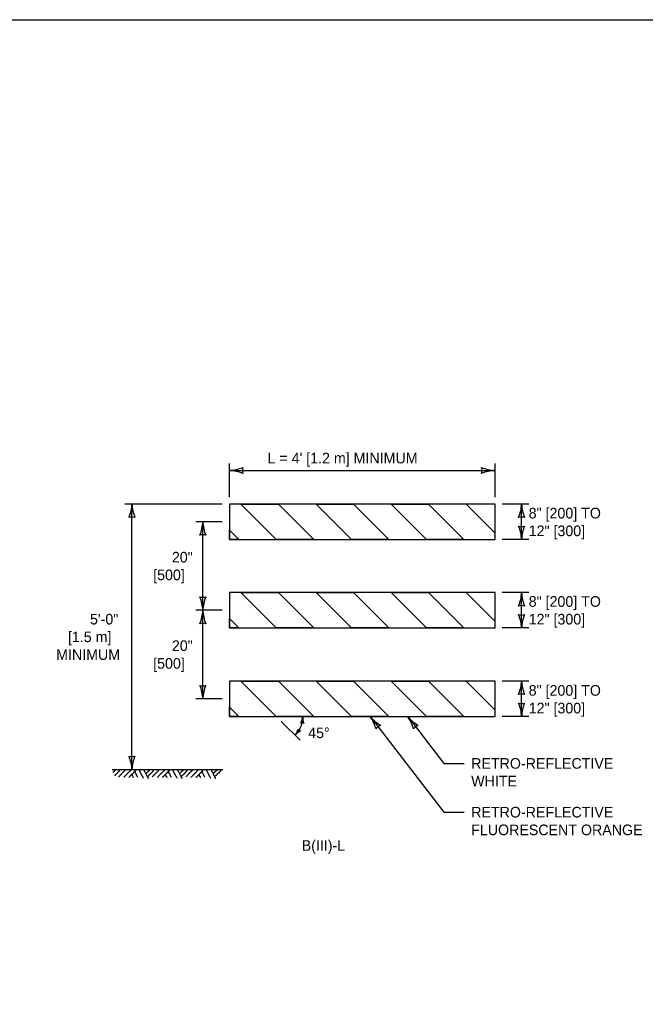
# Model space of a CAD drawing. Extents: x 49991.4 to 50021, y 49987.6 to 50011.4.
# Drawn here: x 50005.22 to 50008.75, y 49993.4 to 49999 of the extents above; entities that cross this region are included whole.
import ezdxf

# ---------------------------------------------------------------- set-up
doc = ezdxf.new("R2010")
doc.units = 0
for name, color, linetype in [('Level 1', 7, 'Continuous'), ('Level 2', 7, 'Continuous'), ('Level 3', 7, 'Continuous')]:
    doc.layers.add(name, color=color, linetype=linetype)

msp = doc.modelspace()

# ---------------------------------------------------------------- linework, layer by layer
at = {"layer": 'Level 1'}
for p, q in [((50006.6636, 49996.0636), (50006.464, 49996.2636)), ((50006.6636, 49996.0636), (50006.464, 49996.2636)), ((50006.8756, 49996.0636), (50006.676, 49996.2636)), ((50006.676, 49996.2636), (50006.8756, 49996.0636)), ((50007.0875, 49996.0636), (50006.8879, 49996.2636)), ((50007.0875, 49996.0636), (50006.8879, 49996.2636)), ((50007.2995, 49996.0636), (50007.0999, 49996.2636)), ((50007.0999, 49996.2636), (50007.2995, 49996.0636)), ((50007.5114, 49996.0636), (50007.3118, 49996.2636)), ((50007.5114, 49996.0636), (50007.3118, 49996.2636)), ((50007.7234, 49996.0636), (50007.5238, 49996.2636)), ((50007.5238, 49996.2636), (50007.7234, 49996.0636)), ((50007.8988, 49996.1002), (50007.7357, 49996.2636)), ((50007.7357, 49996.2636), (50007.8988, 49996.1002)), ((50006.4517, 49996.0636), (50006.3988, 49996.1166)), ((50006.3988, 49996.1166), (50006.4517, 49996.0636)), ((50006.6636, 49995.5636), (50006.464, 49995.7636)), ((50006.6636, 49995.5636), (50006.464, 49995.7636)), ((50006.8756, 49995.5636), (50006.676, 49995.7636)), ((50006.676, 49995.7636), (50006.8756, 49995.5636)), ((50007.0875, 49995.5636), (50006.8879, 49995.7636)), ((50007.0875, 49995.5636), (50006.8879, 49995.7636)), ((50007.2995, 49995.5636), (50007.0999, 49995.7636)), ((50007.0999, 49995.7636), (50007.2995, 49995.5636)), ((50007.5114, 49995.5636), (50007.3118, 49995.7636)), ((50007.5114, 49995.5636), (50007.3118, 49995.7636)), ((50007.7234, 49995.5636), (50007.5238, 49995.7636)), ((50007.5238, 49995.7636), (50007.7234, 49995.5636)), ((50007.8988, 49995.6002), (50007.7357, 49995.7636)), ((50007.7357, 49995.7636), (50007.8988, 49995.6002)), ((50006.4517, 49995.5636), (50006.3988, 49995.6166)), ((50006.3988, 49995.6166), (50006.4517, 49995.5636)), ((50006.6636, 49995.0636), (50006.464, 49995.2636)), ((50006.6636, 49995.0636), (50006.464, 49995.2636)), ((50006.8756, 49995.0636), (50006.676, 49995.2636)), ((50006.676, 49995.2636), (50006.8756, 49995.0636)), ((50007.0875, 49995.0636), (50006.8879, 49995.2636)), ((50007.0875, 49995.0636), (50006.8879, 49995.2636)), ((50007.2995, 49995.0636), (50007.0999, 49995.2636)), ((50007.0999, 49995.2636), (50007.2995, 49995.0636)), ((50007.5114, 49995.0636), (50007.3118, 49995.2636)), ((50007.5114, 49995.0636), (50007.3118, 49995.2636)), ((50007.7234, 49995.0636), (50007.5238, 49995.2636)), ((50007.5238, 49995.2636), (50007.7234, 49995.0636)), ((50007.8988, 49995.1002), (50007.7357, 49995.2636)), ((50007.7357, 49995.2636), (50007.8988, 49995.1002)), ((50006.4517, 49995.0636), (50006.3988, 49995.1166)), ((50006.3988, 49995.1166), (50006.4517, 49995.0636))]:
    msp.add_line(p, q, dxfattribs=at)
for points in [[(49999.3835, 49998.9992), (50016.7501, 49998.9992), (50016.7501, 49987.7988), (49999.3835, 49987.7988)], [(50007.8988, 49996.2636), (50006.3988, 49996.2636), (50006.3988, 49996.0636), (50007.8988, 49996.0636)], [(50007.8988, 49995.7636), (50006.3988, 49995.7636), (50006.3988, 49995.5636), (50007.8988, 49995.5636)], [(50007.8988, 49995.2636), (50006.3988, 49995.2636), (50006.3988, 49995.0636), (50007.8988, 49995.0636)]]:
    msp.add_lwpolyline(points, close=True, dxfattribs=at)
for points in [[(50006.464, 49996.2636), (50006.676, 49996.2636)], [(50006.8879, 49996.2636), (50007.0999, 49996.2636)], [(50007.3118, 49996.2636), (50007.5238, 49996.2636)], [(50007.8988, 49996.1002), (50007.8988, 49996.2636), (50007.7357, 49996.2636)], [(50006.4517, 49996.0636), (50006.3988, 49996.0636), (50006.3988, 49996.1166)], [(50006.8756, 49996.0636), (50006.6636, 49996.0636)], [(50007.2995, 49996.0636), (50007.0875, 49996.0636)], [(50007.7234, 49996.0636), (50007.5114, 49996.0636)], [(50006.464, 49995.7636), (50006.676, 49995.7636)], [(50006.8879, 49995.7636), (50007.0999, 49995.7636)], [(50007.3118, 49995.7636), (50007.5238, 49995.7636)], [(50007.8988, 49995.6002), (50007.8988, 49995.7636), (50007.7357, 49995.7636)], [(50006.4517, 49995.5636), (50006.3988, 49995.5636), (50006.3988, 49995.6166)], [(50006.8756, 49995.5636), (50006.6636, 49995.5636)], [(50007.2995, 49995.5636), (50007.0875, 49995.5636)], [(50007.7234, 49995.5636), (50007.5114, 49995.5636)], [(50006.464, 49995.2636), (50006.676, 49995.2636)], [(50006.8879, 49995.2636), (50007.0999, 49995.2636)], [(50007.3118, 49995.2636), (50007.5238, 49995.2636)], [(50007.8988, 49995.1002), (50007.8988, 49995.2636), (50007.7357, 49995.2636)], [(50006.4517, 49995.0636), (50006.3988, 49995.0636), (50006.3988, 49995.1166)], [(50006.8756, 49995.0636), (50006.6636, 49995.0636)], [(50007.2995, 49995.0636), (50007.0875, 49995.0636)], [(50007.7234, 49995.0636), (50007.5114, 49995.0636)], [(50005.7556, 49994.7636), (50005.7554, 49994.761), (50005.7522, 49994.7583), (50005.7521, 49994.7568), (50005.7506, 49994.757), (50005.7489, 49994.7542), (50005.7475, 49994.7543), (50005.7473, 49994.7528), (50005.7442, 49994.7502), (50005.7441, 49994.7488), (50005.7426, 49994.7489), (50005.741, 49994.7462)], [(50005.7858, 49994.7636), (50005.7769, 49994.7562), (50005.7768, 49994.7547), (50005.7754, 49994.7548), (50005.7737, 49994.7521), (50005.7707, 49994.7508), (50005.7688, 49994.7467), (50005.7658, 49994.7454), (50005.7657, 49994.744), (50005.7625, 49994.7413), (50005.7624, 49994.7398), (50005.7609, 49994.7399), (50005.7592, 49994.7372), (50005.7578, 49994.7373), (50005.7576, 49994.7359), (50005.7545, 49994.7332), (50005.7544, 49994.7317), (50005.7529, 49994.7319), (50005.7512, 49994.729)], [(50005.8129, 49994.7636), (50005.8067, 49994.7566), (50005.8066, 49994.7551), (50005.8051, 49994.7552), (50005.8034, 49994.7524), (50005.7987, 49994.7484), (50005.7985, 49994.747), (50005.797, 49994.7472), (50005.7953, 49994.7444), (50005.7924, 49994.7431), (50005.7905, 49994.7389), (50005.7875, 49994.7376), (50005.7874, 49994.7362), (50005.7841, 49994.7336), (50005.784, 49994.7321), (50005.7826, 49994.7322), (50005.7809, 49994.7295), (50005.7795, 49994.7296), (50005.7793, 49994.7281), (50005.7762, 49994.7255), (50005.7761, 49994.724), (50005.7746, 49994.7241), (50005.7728, 49994.7213)], [(50005.8444, 49994.7636), (50005.8362, 49994.7544), (50005.8361, 49994.7529), (50005.8346, 49994.7531), (50005.8328, 49994.7503), (50005.8282, 49994.7463), (50005.8281, 49994.7449), (50005.8266, 49994.745), (50005.8249, 49994.7421), (50005.8218, 49994.741), (50005.82, 49994.7367), (50005.817, 49994.7355), (50005.8169, 49994.7341), (50005.8137, 49994.7315), (50005.8135, 49994.73), (50005.8121, 49994.7301), (50005.8104, 49994.7273), (50005.8089, 49994.7275), (50005.8088, 49994.726), (50005.8056, 49994.7233), (50005.8055, 49994.7218), (50005.8041, 49994.722), (50005.8024, 49994.7192)], [(50005.8731, 49994.7636), (50005.8644, 49994.7538), (50005.8642, 49994.7524), (50005.8627, 49994.7525), (50005.8611, 49994.7497), (50005.8563, 49994.7457), (50005.8562, 49994.7443), (50005.8547, 49994.7444), (50005.8531, 49994.7416), (50005.8501, 49994.7404), (50005.8482, 49994.7361), (50005.8451, 49994.7349), (50005.845, 49994.7335), (50005.8418, 49994.7309), (50005.8417, 49994.7294), (50005.8403, 49994.7295), (50005.8385, 49994.7267), (50005.8372, 49994.7268), (50005.837, 49994.7254), (50005.8338, 49994.7227), (50005.8337, 49994.7213), (50005.8323, 49994.7214), (50005.8305, 49994.7186)], [(50005.8475, 49994.7376), (50005.851, 49994.7271), (50005.8539, 49994.7254), (50005.8563, 49994.7194)], [(50005.864, 49994.7538), (50005.8675, 49994.7433), (50005.8702, 49994.7416), (50005.8751, 49994.7294), (50005.8765, 49994.7293), (50005.8778, 49994.7263), (50005.8776, 49994.7248), (50005.8803, 49994.7216), (50005.8806, 49994.7209)], [(50005.8885, 49994.7636), (50005.8931, 49994.7502), (50005.8958, 49994.7485), (50005.9006, 49994.7363), (50005.9021, 49994.7362), (50005.9032, 49994.7333), (50005.9031, 49994.7318), (50005.9058, 49994.7287), (50005.9081, 49994.7226), (50005.9096, 49994.7224), (50005.9122, 49994.7161)], [(50005.916, 49994.7636), (50005.9196, 49994.7527), (50005.9223, 49994.751), (50005.9272, 49994.7389), (50005.9287, 49994.7388), (50005.9299, 49994.7357), (50005.9297, 49994.7342), (50005.9324, 49994.7311), (50005.9349, 49994.725), (50005.9362, 49994.7249), (50005.9399, 49994.7158), (50005.9428, 49994.7156)], [(50005.95, 49994.7636), (50005.9438, 49994.7565), (50005.9437, 49994.755), (50005.9422, 49994.7552), (50005.9405, 49994.7524), (50005.9357, 49994.7484), (50005.9355, 49994.747), (50005.9341, 49994.7471), (50005.9324, 49994.7443), (50005.9294, 49994.7431), (50005.9287, 49994.7415)], [(50005.9755, 49994.7636), (50005.9654, 49994.7525), (50005.9653, 49994.751), (50005.9638, 49994.7511), (50005.9622, 49994.7483), (50005.9574, 49994.7444), (50005.9573, 49994.7429), (50005.9558, 49994.7431), (50005.9541, 49994.7403), (50005.9511, 49994.739), (50005.9492, 49994.7348), (50005.9461, 49994.7336), (50005.946, 49994.7321), (50005.9429, 49994.7294), (50005.9427, 49994.728), (50005.9413, 49994.7281), (50005.9396, 49994.7254), (50005.9382, 49994.7255), (50005.9382, 49994.7251)], [(50006.0026, 49994.7636), (50005.9964, 49994.7566), (50005.9963, 49994.7551), (50005.9948, 49994.7552), (50005.9931, 49994.7524), (50005.9884, 49994.7484), (50005.9882, 49994.747), (50005.9867, 49994.7472), (50005.985, 49994.7444), (50005.9821, 49994.7431), (50005.9802, 49994.7389), (50005.9772, 49994.7376), (50005.9771, 49994.7362), (50005.9738, 49994.7336), (50005.9737, 49994.7321), (50005.9723, 49994.7322), (50005.9706, 49994.7295), (50005.9692, 49994.7296), (50005.969, 49994.7281), (50005.9659, 49994.7255), (50005.9658, 49994.724), (50005.9643, 49994.7241), (50005.9625, 49994.7213)], [(50006.0341, 49994.7636), (50006.0259, 49994.7544), (50006.0258, 49994.7529), (50006.0243, 49994.7531), (50006.0225, 49994.7503), (50006.0179, 49994.7463), (50006.0178, 49994.7449), (50006.0163, 49994.745), (50006.0146, 49994.7421), (50006.0115, 49994.741), (50006.0097, 49994.7367), (50006.0067, 49994.7355), (50006.0066, 49994.7341), (50006.0034, 49994.7315), (50006.0032, 49994.73), (50006.0018, 49994.7301), (50006.0001, 49994.7273), (50005.9986, 49994.7275), (50005.9985, 49994.726), (50005.9953, 49994.7233), (50005.9952, 49994.7218), (50005.9938, 49994.722), (50005.9921, 49994.7192)], [(50006.0628, 49994.7636), (50006.0541, 49994.7538), (50006.0539, 49994.7524), (50006.0524, 49994.7525), (50006.0508, 49994.7497), (50006.046, 49994.7457), (50006.0459, 49994.7443), (50006.0444, 49994.7444), (50006.0428, 49994.7416), (50006.0398, 49994.7404), (50006.0379, 49994.7361), (50006.0348, 49994.7349), (50006.0347, 49994.7335), (50006.0315, 49994.7309), (50006.0314, 49994.7294), (50006.03, 49994.7295), (50006.0282, 49994.7267), (50006.0269, 49994.7268), (50006.0267, 49994.7254), (50006.0235, 49994.7227), (50006.0234, 49994.7213), (50006.022, 49994.7214), (50006.0202, 49994.7186)], [(50006.0372, 49994.7376), (50006.0407, 49994.7271), (50006.0436, 49994.7254), (50006.046, 49994.7194)], [(50006.0537, 49994.7538), (50006.0572, 49994.7433), (50006.0599, 49994.7416), (50006.0648, 49994.7294), (50006.0662, 49994.7293), (50006.0675, 49994.7263), (50006.0673, 49994.7248), (50006.07, 49994.7216), (50006.0703, 49994.7209)], [(50006.0782, 49994.7636), (50006.0828, 49994.7502), (50006.0855, 49994.7485), (50006.0903, 49994.7363), (50006.0918, 49994.7362), (50006.0929, 49994.7333), (50006.0928, 49994.7318), (50006.0955, 49994.7287), (50006.0978, 49994.7226), (50006.0993, 49994.7224), (50006.1019, 49994.7161)], [(50006.1057, 49994.7636), (50006.1093, 49994.7527), (50006.112, 49994.751), (50006.1169, 49994.7389), (50006.1184, 49994.7388), (50006.1196, 49994.7357), (50006.1194, 49994.7342), (50006.1221, 49994.7311), (50006.1246, 49994.725), (50006.1259, 49994.7249), (50006.1296, 49994.7158), (50006.1325, 49994.7156)], [(50006.1397, 49994.7636), (50006.1335, 49994.7565), (50006.1334, 49994.755), (50006.1319, 49994.7552), (50006.1302, 49994.7524), (50006.1254, 49994.7484), (50006.1252, 49994.747), (50006.1238, 49994.7471), (50006.1221, 49994.7443), (50006.1191, 49994.7431), (50006.1184, 49994.7415)], [(50006.1652, 49994.7636), (50006.1551, 49994.7525), (50006.155, 49994.751), (50006.1535, 49994.7511), (50006.1519, 49994.7483), (50006.1471, 49994.7444), (50006.147, 49994.7429), (50006.1455, 49994.7431), (50006.1438, 49994.7403), (50006.1408, 49994.739), (50006.1389, 49994.7348), (50006.1358, 49994.7336), (50006.1357, 49994.7321), (50006.1326, 49994.7294), (50006.1324, 49994.728), (50006.131, 49994.7281), (50006.1293, 49994.7254), (50006.1279, 49994.7255), (50006.1279, 49994.7251)], [(50006.1923, 49994.7636), (50006.1861, 49994.7566), (50006.186, 49994.7551), (50006.1845, 49994.7552), (50006.1828, 49994.7524), (50006.1781, 49994.7484), (50006.1779, 49994.747), (50006.1764, 49994.7472), (50006.1747, 49994.7444), (50006.1718, 49994.7431), (50006.1699, 49994.7389), (50006.1669, 49994.7376), (50006.1668, 49994.7362), (50006.1635, 49994.7336), (50006.1634, 49994.7321), (50006.162, 49994.7322), (50006.1603, 49994.7295), (50006.1589, 49994.7296), (50006.1587, 49994.7281), (50006.1556, 49994.7255), (50006.1555, 49994.724), (50006.154, 49994.7241), (50006.1522, 49994.7213)], [(50006.2238, 49994.7636), (50006.2156, 49994.7544), (50006.2155, 49994.7529), (50006.214, 49994.7531), (50006.2122, 49994.7503), (50006.2076, 49994.7463), (50006.2075, 49994.7449), (50006.206, 49994.745), (50006.2043, 49994.7421), (50006.2012, 49994.741), (50006.1994, 49994.7367), (50006.1964, 49994.7355), (50006.1963, 49994.7341), (50006.1931, 49994.7315), (50006.1929, 49994.73), (50006.1915, 49994.7301), (50006.1898, 49994.7273), (50006.1883, 49994.7275), (50006.1882, 49994.726), (50006.185, 49994.7233), (50006.1849, 49994.7218), (50006.1835, 49994.722), (50006.1818, 49994.7192)], [(50006.2525, 49994.7636), (50006.2438, 49994.7538), (50006.2436, 49994.7524), (50006.2421, 49994.7525), (50006.2405, 49994.7497), (50006.2357, 49994.7457), (50006.2356, 49994.7443), (50006.2341, 49994.7444), (50006.2325, 49994.7416), (50006.2295, 49994.7404), (50006.2276, 49994.7361), (50006.2245, 49994.7349), (50006.2244, 49994.7335), (50006.2212, 49994.7309), (50006.2211, 49994.7294), (50006.2197, 49994.7295), (50006.2179, 49994.7267), (50006.2166, 49994.7268), (50006.2164, 49994.7254), (50006.2132, 49994.7227), (50006.2131, 49994.7213), (50006.2117, 49994.7214), (50006.2099, 49994.7186)], [(50006.2269, 49994.7376), (50006.2304, 49994.7271), (50006.2333, 49994.7254), (50006.2357, 49994.7194)], [(50006.2434, 49994.7538), (50006.2469, 49994.7433), (50006.2496, 49994.7416), (50006.2545, 49994.7294), (50006.2559, 49994.7293), (50006.2572, 49994.7263), (50006.257, 49994.7248), (50006.2597, 49994.7216), (50006.26, 49994.7209)], [(50006.2679, 49994.7636), (50006.2725, 49994.7502), (50006.2752, 49994.7485), (50006.28, 49994.7363), (50006.2815, 49994.7362), (50006.2826, 49994.7333), (50006.2825, 49994.7318), (50006.2852, 49994.7287), (50006.2875, 49994.7226), (50006.289, 49994.7224), (50006.2916, 49994.7161)], [(50006.2954, 49994.7636), (50006.299, 49994.7527), (50006.3017, 49994.751), (50006.3066, 49994.7389), (50006.3081, 49994.7388), (50006.3093, 49994.7357), (50006.3091, 49994.7342), (50006.3118, 49994.7311), (50006.3143, 49994.725), (50006.3156, 49994.7249), (50006.3193, 49994.7158), (50006.3222, 49994.7156)], [(50006.3294, 49994.7636), (50006.3232, 49994.7565), (50006.3231, 49994.755), (50006.3216, 49994.7552), (50006.3199, 49994.7524), (50006.3151, 49994.7484), (50006.3149, 49994.747), (50006.3135, 49994.7471), (50006.3118, 49994.7443), (50006.3088, 49994.7431), (50006.3081, 49994.7415)], [(50006.3549, 49994.7636), (50006.3448, 49994.7525), (50006.3447, 49994.751), (50006.3432, 49994.7511), (50006.3416, 49994.7483), (50006.3368, 49994.7444), (50006.3367, 49994.7429), (50006.3352, 49994.7431), (50006.3335, 49994.7403), (50006.3305, 49994.739), (50006.3286, 49994.7348), (50006.3255, 49994.7336), (50006.3254, 49994.7321), (50006.3223, 49994.7294), (50006.3221, 49994.728), (50006.3207, 49994.7281), (50006.319, 49994.7254), (50006.3176, 49994.7255), (50006.3176, 49994.7251)]]:
    msp.add_lwpolyline(points, dxfattribs=at)
at = {"layer": 'Level 2'}
msp.add_line((50005.7367, 49994.7636), (50006.3609, 49994.7636), dxfattribs=at)
at = {"layer": 'Level 3'}
for p, q in [((50006.3988, 49996.3036), (50006.3988, 49996.4936)), ((50007.8988, 49996.3036), (50007.8988, 49996.4936)), ((50006.3988, 49996.4536), (50007.8988, 49996.4536)), ((50006.3588, 49996.2636), (50005.8088, 49996.2636)), ((50005.8488, 49994.7636), (50005.8488, 49996.2636)), ((50008.0888, 49996.2636), (50007.9388, 49996.2636)), ((50008.0488, 49996.0636), (50008.0488, 49996.2636)), ((50006.3588, 49996.1636), (50006.2088, 49996.1636)), ((50006.2488, 49995.6636), (50006.2488, 49996.1636)), ((50008.0888, 49996.0636), (50007.9388, 49996.0636)), ((50008.0888, 49995.7636), (50007.9388, 49995.7636)), ((50008.0488, 49995.5636), (50008.0488, 49995.7636)), ((50006.3588, 49995.6636), (50006.2088, 49995.6636)), ((50006.2488, 49995.1636), (50006.2488, 49995.6636)), ((50008.0888, 49995.5636), (50007.9388, 49995.5636)), ((50008.0888, 49995.2636), (50007.9388, 49995.2636)), ((50008.0488, 49995.0636), (50008.0488, 49995.2636)), ((50006.3588, 49995.1636), (50006.2088, 49995.1636)), ((50007.1936, 49995.0636), (50007.6094, 49994.5232)), ((50007.4054, 49995.0636), (50007.6094, 49994.7987)), ((50008.0888, 49995.0636), (50007.9388, 49995.0636)), ((50006.6919, 49995.0353), (50006.7981, 49994.9294)), ((50007.6094, 49994.7987), (50007.7241, 49994.7987)), ((50007.6094, 49994.5232), (50007.7241, 49994.5232))]:
    msp.add_line(p, q, dxfattribs=at)
for centre, radius, start, end in [((50006.3873, 49996.6863), 0.233, 272.8273, 292.0772), ((50006.527, 49996.4536), 0.0548, 162.1388, 197.8612), ((50007.9079, 49996.6757), 0.2223, 247.456, 267.6395), ((50007.7706, 49996.4536), 0.0548, 342.1388, 17.8612), ((50006.3896, 49996.2314), 0.2223, 67.456, 87.6395), ((50007.9103, 49996.2208), 0.233, 92.8273, 112.0772), ((50005.6267, 49996.2727), 0.2223, 337.456, 357.6395), ((50006.0815, 49996.275), 0.233, 182.8273, 202.0772), ((50007.8267, 49996.2727), 0.2223, 337.456, 357.6395), ((50008.2815, 49996.275), 0.233, 182.8273, 202.0772), ((50005.8488, 49996.1353), 0.0548, 72.1388, 107.8612), ((50008.0488, 49996.1353), 0.0548, 72.1388, 107.8612), ((50006.0267, 49996.1727), 0.2223, 337.456, 357.6395), ((50006.4815, 49996.175), 0.233, 182.8273, 202.0772), ((50008.0488, 49996.1918), 0.0548, 252.1388, 287.8612), ((50007.8161, 49996.0521), 0.233, 2.8273, 22.0772), ((50008.2709, 49996.0544), 0.2223, 157.456, 177.6395), ((50006.2488, 49996.0353), 0.0548, 72.1388, 107.8612), ((50006.2488, 49995.7918), 0.0548, 252.1388, 287.8612), ((50006.0161, 49995.6521), 0.233, 2.8273, 22.0772), ((50006.4709, 49995.6544), 0.2223, 157.456, 177.6395), ((50007.8267, 49995.7727), 0.2223, 337.456, 357.6395), ((50008.2815, 49995.775), 0.233, 182.8273, 202.0772), ((50008.0488, 49995.6353), 0.0548, 72.1388, 107.8612), ((50006.0267, 49995.6727), 0.2223, 337.456, 357.6395), ((50006.4815, 49995.675), 0.233, 182.8273, 202.0772), ((50008.0488, 49995.6918), 0.0548, 252.1388, 287.8612), ((50007.8161, 49995.5521), 0.233, 2.8273, 22.0772), ((50008.2709, 49995.5544), 0.2223, 157.456, 177.6395), ((50006.2488, 49995.5353), 0.0548, 72.1388, 107.8612), ((50006.2488, 49995.2918), 0.0548, 252.1388, 287.8612), ((50006.0161, 49995.1521), 0.233, 2.8273, 22.0772), ((50006.4709, 49995.1544), 0.2223, 157.456, 177.6395), ((50007.8267, 49995.2727), 0.2223, 337.456, 357.6395), ((50008.2815, 49995.275), 0.233, 182.8273, 202.0772), ((50008.0488, 49995.1353), 0.0548, 72.1388, 107.8612), ((50008.0488, 49995.1918), 0.0548, 252.1388, 287.8612), ((50007.8161, 49995.0521), 0.233, 2.8273, 22.0772), ((50008.2709, 49995.0544), 0.2223, 157.456, 177.6395), ((50006.6983, 49995.0802), 0.1165, 332.5463, 351.7961), ((50006.9246, 49995.0577), 0.1112, 176.9839, 197.1674), ((50007.012, 49994.9354), 0.2223, 15.0318, 35.2153), ((50007.371, 49995.2146), 0.233, 220.4031, 239.6529), ((50007.2238, 49994.9353), 0.2223, 15.0559, 35.2395), ((50007.5828, 49995.2146), 0.233, 220.4272, 239.6771), ((50006.6636, 49995.0636), 0.15, 320.8129, 356.8027), ((50006.8076, 49994.9997), 0.0274, 66.7622, 102.4846), ((50007.2718, 49994.9619), 0.0548, 109.7146, 145.4369), ((50007.4836, 49994.962), 0.0548, 109.7388, 145.4611), ((50006.6807, 49995.0241), 0.1112, 323.2757, 343.4592), ((50006.8565, 49994.8798), 0.1165, 118.838, 138.0879), ((50006.8102, 49995.0074), 0.0274, 213.054, 248.7764), ((50005.8488, 49994.8918), 0.0548, 252.1388, 287.8612), ((50005.6161, 49994.7521), 0.233, 2.8273, 22.0772), ((50006.0709, 49994.7544), 0.2223, 157.456, 177.6395)]:
    msp.add_arc(centre, radius, start, end, dxfattribs=at)

# ---------------------------------------------------------------- texts
at = {"layer": 'Level 2'}
for s, p in [("L = 4' [1.2 m] MINIMUM", (50006.6146, 49996.4936)), ('8" [200] TO', (50008.0888, 49996.1825)), ('12" [300]', (50008.0888, 49996.0825)), ('20"', (50006.0742, 49995.9336)), ('[500]', (50005.9684, 49995.8336)), ('8" [200] TO', (50008.0888, 49995.6834)), ('5\'-0"', (50005.6119, 49995.5836)), ('12" [300]', (50008.0888, 49995.5834)), ('[1.5 m]', (50005.4874, 49995.4836)), ('20"', (50006.0742, 49995.4336)), ('MINIMUM', (50005.4207, 49995.3836)), ('[500]', (50005.9684, 49995.3336)), ('8" [200] TO', (50008.0888, 49995.1811)), ('12" [300]', (50008.0888, 49995.0811)), ('45°', (50006.8437, 49994.9414)), ('RETRO-REFLECTIVE', (50007.7641, 49994.7687)), ('WHITE', (50007.7641, 49994.6687)), ('RETRO-REFLECTIVE', (50007.7641, 49994.4932)), ('FLUORESCENT ORANGE', (50007.7641, 49994.3932)), ('B(III)-L', (50006.8071, 49994.305))]:
    msp.add_text(s, height=0.06, dxfattribs=at).set_placement(p)

doc.saveas('drawing.dxf')
